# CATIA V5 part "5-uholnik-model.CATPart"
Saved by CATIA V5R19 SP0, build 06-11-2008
Part number: 5-uholnik
Bounding box of the stored display mesh (mm): x -75.34 to -64.711, y -24.373 to 24.372, z -12.001 to 34.252
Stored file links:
  G:\Dokumenty od 01.06.2010\CATIA V5 R19 dokumenty\Lopta\5-uholnik-model.CATPart
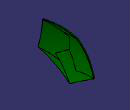
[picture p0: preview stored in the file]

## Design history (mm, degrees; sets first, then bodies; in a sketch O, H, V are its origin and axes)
Body1 (main body)
  DatumPoint1
  DatumPoint2
  Line1: type PtPt, SecondPoint DatumPoint2, FirstPoint DatumPoint1
  Plane1: stored without definition
  DatumCurve1
  Line2: type PtDir, Direction DatumCurve1, Start 0, End 100, RefPoint vertex of Line1
  Line3: type Angle, Angle 190, Curve Line1, Start 0, End 100, RefPoint vertex of Line2
  Line4: type PtDir, Direction Line2, Start 0, End 200, RefPoint vertex of Line3
  Line5: type PtDir, Direction Line2, Start 0, End 100, RefPoint vertex of Line1
  Line6: type PtDir, Direction Line3, Start 0, End 100, RefPoint vertex of Line5
  Fill1: Boundary (Line4; Line3; Line2; Line5; Line6)
  DatumPoint3
  Line7: type PtPt, SecondPoint vertex of Line1, FirstPoint DatumPoint3
  DatumPoint4
  DatumPoint5
  Line8: type PtPt, SecondPoint DatumPoint5, FirstPoint DatumPoint4
  DatumPoint6
  Line9: type PtPt, SecondPoint vertex of Line8, FirstPoint DatumPoint6
  Point1: type OnCurve, Support Line9, Length 15
  Line10: type PtPt, SecondPoint vertex of Line1, FirstPoint Point1
  Point2: type OnCurve, Support Line8, Length 15
  Line11: type PtPt, SecondPoint Point2, FirstPoint vertex of Line7
  Circle1: type 2PointsRad, Start 0, End 180, Support Fill1, SecondPoint vertex of Line1, Radius 74.341, FirstPoint vertex of Line7
  Line12: type PtDir, Direction Line7, Start 0, End 1, RefPoint vertex of Line7
  Line13: type PtDir, Direction Line1, Start 0, End 1, RefPoint vertex of Line1
  Circle2: type 2PointsRad, Start 0, End 180, Support Fill1, SecondPoint vertex of Line13, Radius 75.341, FirstPoint vertex of Line12
  Join1: Elements (Line13; Circle2; Line12; Circle1)
  Fill2: Boundary Join1
  Point3: type OnCurve, Support DatumCurve1, Length 15
  Line14: type PtPt, SecondPoint Point3, FirstPoint DatumPoint1
  Line15: type PtDir, Direction Line14, Start 0, End 75.341, RefPoint DatumPoint1
  Point4: (0, 0, 0), relative to vertex of Line15
  Line16: type PtPt, SecondPoint DatumPoint6, FirstPoint DatumPoint4
  DatumSurface1
  Line17: type PtDir, Direction DatumSurface1, Start 0, End 75.341, RefPoint DatumPoint1
  Line18: type PtPt, SecondPoint Point4, FirstPoint vertex of Line17
  Plane2: type 3Points, Element1 DatumPoint1, Element2 vertex of Line17, Element3 Point4
  Circle3: type 2PointsRad, Start 0, End 180, Support Plane2, SecondPoint vertex of Line17, Radius 75.341, FirstPoint Point4
  Boundary1: Boundary Fill2
  Rib1: profile Boundary1, centre curve Circle3
  CircPattern1: of the body so far, instances 5, angular step 72, axis from Line17
  Fillet1: radius 0.8, on edge [face of Rib1 | face of Rib1]; edge [face of CircPattern1 | face of CircPattern1] (x4)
